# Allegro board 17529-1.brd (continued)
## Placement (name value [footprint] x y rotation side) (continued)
R2614  100R2F-L1-GP-U  [R402H14]  82.17 10.79 0 top
R2615  4K7R2J-2-GP  [R402H16]  87.44 10.22 270 top
R2616  2K2R2J-2-GP  [R402H16]  78.87 10.86 0 top
R2617  8K2R2F-1-GP  [R402H16]  85.72 12.7 180 top
R2618  20KR2J-L2-GP  [R402H16]  85.72 10.67 180 top
R2619  100KR2J-1-GP  [R402H16]  88.01 18.41 90 top
R2701  10KR2J-3-GP  [R402H16]  68.83 235.84 180 top
R2702  47KR2J-2-GP  [R402H16]  74.37 225.3 0 top
R2703  33R2J-2-GP  [R402H16]  61.52 223.85 270 top
R2704  4K7R2J-2-GP  [R402H16]  73.23 225.3 0 top
R2705  0R0603-PAD-2-GP-U  [0R0603-PAD-1-U]  58.42 230 0 bottom
R2706  100KR2F-L1-GP  [R402H16]  50.86 231.01 90 top
R2707  100KR2F-L1-GP  [R402H16]  50.86 232.16 90 top
R2708  0R0603-PAD-2-GP-U  [0R0603-PAD-1-U]  50.93 233.3 90 top
R2709  100KR2F-L1-GP  [R402H16]  53.72 231.01 0 top
R2710  200KR2F-L-GP  [R402H16]  54.74 231.01 0 top
R2711  100KR2F-L1-GP  [R402H16]  53.72 232.92 180 top
R2712  200KR2F-L-GP  [R402H16]  54.74 232.92 180 top
R2713  0R0603-PAD-2-GP-U  [0R0603-PAD-1-U]  76.2 230.5 270 top
R2714  220KR2F-GP  [R402H16]  79.63 235.46 90 top
R2715  0R2J-2-GP  [R402H16]  79.63 233.43 90 top
R2716  10KR2J-3-GP  [R402H16]  79.63 234.44 270 top
R2717  10KR2J-3-GP  [R402H16]  51.44 225.04 0 top
R2718  1KR2J-1-GP  [R402H16]  65.02 224.6 0 top
R2719  1KR2J-1-GP  [R402H16]  51.21 228.5 180 top
R2901  2K2R2J-2-GP  [R402H16]  70.23 227.33 90 top
R2902  1KR2J-1-GP  [R402H16]  72.77 227.33 270 top
R2903  4K7R2J-2-GP  [R402H16]  67.69 241.3 90 top
R2904  4K7R2J-2-GP  [R402H16]  67.69 240.28 90 top
R2905  10R2F-L-GP  [R402H14]  71.75 241.81 180 top
R2906  10R2F-L-GP  [R402H14]  71.75 239.78 0 top
R2907  22KR2J-GP  [R402H16]  68.71 242.82 180 top
R2908  1KR2J-1-GP  [R402H16]  77.09 239.4 180 top
R2909  22KR2J-GP  [R402H16]  75.95 242.57 180 top
R2910  1KR2J-1-GP  [R402H16]  76.58 237.87 270 top
R3001  75R2F-2-GP  [R402H16]  12.37 21.92 180 top
R3002  75R2F-2-GP  [R402H16]  11.96 24.85 180 top
R3003  22KR2J-GP  [R402H16]  11.35 21.93 0 top
R3004  22KR2J-GP  [R402H16]  10.95 24.85 0 top
R3005  75R2F-2-GP  [R402H16]  21.08 29.34 0 top
R3006  75R2F-2-GP  [R402H16]  18.03 29.34 0 top
R3007  22KR2J-GP  [R402H16]  18.35 19.3 270 top
R3008  1KR2J-1-GP  [R402H16]  20.07 29.59 0 top
R3009  22KR2J-GP  [R402H16]  18.41 22.35 270 top
R3010  1KR2J-1-GP  [R402H16]  19.05 29.59 0 top
R3011  2K2R2J-2-GP  [R402H16]  17.02 32.08 0 top
R3012  2K2R2J-2-GP  [R402H16]  13.97 32.08 0 top
R3013  75R2F-2-GP  [R402H16]  16 32.08 0 top
R3014  75R2F-2-GP  [R402H16]  14.99 32.08 0 top
R3015  22KR2J-GP  [R402H16]  13.97 30.2 0 top
R3016  22KR2J-GP  [R402H16]  17.02 30.2 0 top
R3101  2K49R2F-GP  [R402H16]  134.37 37.59 90 top
R3102  0R0402-PAD-2-GP  [0R0402-PAD-1]  146.69 41.27 90 top
R3103  1KR2F-3-GP  [R402H16]  144.37 46.69 270 top
R3104  1MR3F-GP  [R603H22]  135.97 42.95 180 top
R3105  0R0603-PAD-2-GP-U  [0R0603-PAD-1-U]  133.86 49.4 180 top
R3106  15KR2F-GP  [R402H16]  142.37 45.47 270 top
R3107  680R2F-GP  [R402H16]  134.85 42.24 0 top
R3201  249R2F-GP  [R402H16]  130.96 32.74 180 top
R3202  249R2F-GP  [R402H16]  129.9 32.74 180 top
R3203  0R1210-PAD-GP  [0R1210-4P-PAD]  137.31 32.95 90 top
R3204  510R3J-2-GP  [R603H22]  132.49 33.03 180 top
R3205  0R1210-PAD-GP  [0R1210-4P-PAD]  139.47 32.95 90 top
R3206  0R1210-PAD-GP  [0R1210-4P-PAD]  141.97 32.94 90 top
R3207  0R1210-PAD-GP  [0R1210-4P-PAD]  144.15 32.94 90 top
R3301  0R0402-PAD-2-GP  [0R0402-PAD-1]  40.39 238 270 top
R3302  6K2R2F-GP  [R402H16]  37.97 228.09 0 top
R3303  0R1210-PAD-GP  [0R1210-4P-PAD]  40.01 226.06 270 top
R3801  0R1210-PAD-GP  [0R1210-4P-PAD]  95.38 235.33 90 top
R3802  0R1210-PAD-GP  [0R1210-4P-PAD]  105.66 235.43 90 top
R3804  0R1210-PAD-GP  [0R1210-4P-PAD]  93.09 235.33 90 top
R3806  0R1210-PAD-GP  [0R1210-4P-PAD]  103.38 235.43 90 top
R3807  10KR2J-3-GP  [R402H16]  107.95 236.27 270 top
R3808  10KR2J-3-GP  [R402H16]  107.95 238.43 90 top
R3809  10KR2J-3-GP  [R402H16]  114.3 238.38 90 top
R3810  22KR2F-GP  [R402H16]  114.3 240.66 90 top
R3811  4K7R2J-2-GP  [R402H16]  110.49 235.46 180 top
R3812  10KR2J-3-GP  [R402H16]  107.95 237.41 90 top
R3813  10KR2J-3-GP  [R402H16]  114.3 236.35 90 top
R3814  0R0402-PAD-2-GP  [0R0402-PAD-1]  114.3 239.52 90 top
R3815  0R2J-2-GP  [R402H16]  111.51 235.46 180 top
R3816  0R2J-2-GP  [R402H16]  107.95 235.13 90 top
R3817  0R2J-2-GP  [R402H16]  114.3 237.36 270 top
R3818  4K7R2J-2-GP  [R402H16]  112.52 235.46 0 top
R4001  10KR2J-3-GP  [R402H16]  96.29 23.34 0 top
R4002  100KR2J-1-GP  [R402H16]  187.63 175.54 180 top
R4003  20KR2J-L2-GP  [R402H16]  89.09 24.77 90 top
R4004  100KR2J-1-GP  [R402H16]  153.8 33.02 0 top
R4005  22KR2J-GP  [R402H16]  99.21 23.22 180 top
R4006  0R0402-PAD-2-GP  [0R0402-PAD-1]  98.07 23.22 180 top
R4007  0R0402-PAD-2-GP  [0R0402-PAD-1]  98.3 28.45 270 top
R4008  0R0402-PAD-2-GP  [0R0402-PAD-1]  187.63 173.51 180 top
R4009  0R0402-PAD-2-GP  [0R0402-PAD-1]  154.05 26.16 180 top
R4010  0R0402-PAD-2-GP  [0R0402-PAD-1]  153.8 19.18 180 top
R4011  22KR2J-GP  [R402H16]  79.71 21.72 90 top
R4013  0R0402-PAD-2-GP  [0R0402-PAD-1]  92.13 22.2 90 top
R4014  249R2F-GP  [R402H16]  76.56 24.33 270 top
R4015  0R0402-PAD-2-GP  [0R0402-PAD-1]  79.73 20.62 90 top
R4016  249R2F-GP  [R402H16]  76.56 25.48 270 top
R4017  8K2R2F-1-GP  [R402H16]  150.24 204.14 90 top
R4018  8K2R2F-1-GP  [R402H16]  146.56 197.1 180 top
R4019  0R0402-PAD-2-GP  [0R0402-PAD-1]  153.29 203.96 90 top
R4020  10KR2J-3-GP  [R402H16]  146.81 204.6 90 top
R4021  0R0402-PAD-2-GP  [0R0402-PAD-1]  147.57 197.1 0 top
R4022  10KR2J-3-GP  [R402H16]  151.51 198.5 180 top
R4023  1KR2J-1-GP  [R402H16]  149.48 198.5 180 top
R4024  0R0402-PAD-2-GP  [0R0402-PAD-1]  144.27 197.1 0 top
R4025  0R0402-PAD-2-GP  [0R0402-PAD-1]  44.2 186.69 180 top
R4026  0R0402-PAD-2-GP  [0R0402-PAD-1]  45.21 186.69 0 top
R4201  0R0402-PAD-2-GP  [0R0402-PAD-1]  87.63 215.65 90 top
R4202  0R0402-PAD-2-GP  [0R0402-PAD-1]  87.63 214.5 90 top
R4203  47KR2J-2-GP  [R402H16]  100.79 211.4 270 top
R4204  10KR2J-3-GP  [R402H16]  96.16 210.24 270 top
R4205  4K7R2J-2-GP  [R402H16]  95.25 207.9 180 top
R4206  100KR2J-1-GP  [R402H16]  102.49 209.45 180 top
R4207  10KR2J-3-GP  [R402H16]  103.68 211 90 top
R4208  220KR2F-GP  [R402H16]  184.25 214.15 0 top
R4209  22KR2F-GP  [R402H16]  194.82 216.15 180 top
R4210  22KR2F-GP  [R402H16]  183.11 214.15 180 top
R4211  200KR2J-L1-GP  [R402H16]  175.21 215.93 270 top
R4212  100KR2F-L1-GP  [R402H16]  174.75 219.58 0 top
R4213  10KR2J-3-GP  [R402H16]  181.23 219.46 90 top
R4214  0R2J-2-GP  [R402H16]  175.21 218.01 270 top
R4215  22KR2F-GP  [R402H16]  175.21 216.99 90 top
R4216  10KR2J-3-GP  [R402H16]  179.71 213.36 90 top
R4217  10KR2F-2-GP  [R402H16]  171.83 220.85 180 top
R4218  100KR2J-1-GP  [R402H16]  175.21 214.83 270 top
R4219  10KR2F-2-GP  [R402H16]  171.45 215.01 270 top
R4302  0R0402-PAD-2-GP  [0R0402-PAD-1]  221.11 215.14 90 top
R4303  0R2J-2-GP  [R402H16]  221.11 216.15 90 top
R4304  10KR2F-2-GP  [R402H16]  215.01 215.26 0 top
R4305  10KR2J-3-GP  [R402H16]  221.11 214 270 top
R4801  10KR2J-3-GP  [R402H16]  134.62 85.72 270 top
R4802  47KR2J-2-GP  [R402H16]  137.92 88.9 270 top
R4803  10KR2J-3-GP  [R402H16]  137.92 87.76 90 top
R5001  0R2J-2-GP  [R402H16]  49.25 186.69 0 top
R5002  0R2J-2-GP  [R402H16]  50.37 186.69 0 top
R5003  0R0402-PAD-2-GP  [0R0402-PAD-1]  51.56 186.69 180 top
R5101  0R0402-PAD-2-GP  [0R0402-PAD-1]  233.22 156.64 0 top
R5301  D15R2010F-GP  [R2010-2H28]  176.15 7.37 180 top
R5302  0R0603-PAD-2-GP-U  [0R0603-PAD-1-U]  179.71 5.71 90 top
R5303  1K96R2F-1-GP  [R402H16]  181.61 13.59 90 top
R5304  16K9R2F-GP  [R402H16]  179.71 13.59 270 top
R5305  4K7R2J-2-GP  [R402H16]  186.31 14.73 180 top
R5601  470R2J-2-GP  [R402H16]  36.3 21.41 180 top
R5602  470R2J-2-GP  [R402H16]  36.3 19.51 0 top
R5603  470R2J-2-GP  [R402H16]  32.89 21.95 270 top
R5604  470R2J-2-GP  [R402H16]  34.8 21.95 90 top
R5605  470R2J-2-GP  [R402H16]  30.07 23.04 270 top
R5606  470R2J-2-GP  [R402H16]  31.98 23.04 90 top
R5607  470R2J-2-GP  [R402H16]  27.23 21.97 270 top
R5608  470R2J-2-GP  [R402H16]  29.13 21.97 90 top
R5609  20KR2F-L-GP  [R402H16]  21.97 15.62 0 top
R5610  1MR2J-1-GP  [R402H16]  23.11 24.21 270 top
R5901  4K7R2J-2-GP  [R402H16]  55.03 23.38 180 top
R5902  4K7R2J-2-GP  [R402H16]  53.95 23.39 180 top
R5903  4K7R2J-2-GP  [R402H16]  68.53 22.38 270 top
R5904  4K7R2J-2-GP  [R402H16]  68.55 23.57 90 top
R5905  4K7R2J-2-GP  [R402H16]  57 25.91 90 top
R5906  4K7R2J-2-GP  [R402H16]  57 24.87 90 top
R5907  4K7R2J-2-GP  [R402H16]  57.4 23.37 180 top
R5908  4K7R2J-2-GP  [R402H16]  55.52 26.31 0 top
R5909  4K7R2J-2-GP  [R402H16]  55.93 28.4 180 top
R5910  100KR2J-1-GP  [R402H16]  67.51 25.37 90 top
R5911  0R0402-PAD-2-GP  [0R0402-PAD-1]  70.89 25.27 180 top
R5912  0R0402-PAD-2-GP  [0R0402-PAD-1]  71.96 25.27 180 top
R5913  75R2F-2-GP  [R402H16]  61.21 18.27 270 top
R5914  75R2F-2-GP  [R402H16]  63.13 18.29 270 top
R5915  75R2F-2-GP  [R402H16]  65.05 18.28 90 top
R5916  47R2F-GP  [R402H16]  57.53 15.24 0 top
R5917  47R2F-GP  [R402H16]  58.67 17.91 0 top
R5918  4K7R2J-2-GP  [R402H16]  69.82 25.27 0 top
R5919  4K7R2J-2-GP  [R402H16]  72.39 23.8 270 top
R5920  10KR2F-2-GP  [R402H16]  42.29 16.26 90 top
R5921  100KR2J-1-GP  [R402H16]  42.29 15.11 270 top
R6202  0R2J-2-GP  [R402H16]  151.18 140.97 180 top
R6203  0R2J-2-GP  [R402H16]  152.32 140.97 180 top
R6301  60K4R2F-GP  [R402H16]  224.05 175.59 0 top
R6302  75KR2F-GP  [R402H16]  224.08 177.95 180 top
R6304  10KR2J-3-GP  [R402H16]  194.41 126.21 0 top
R6306  10KR2J-3-GP  [R402H16]  209.22 210.24 0 top
R6308  0R3J-0-U-GP  [R603H22]  207.26 213.97 90 top
R6311  10KR2J-3-GP  [R402H16]  215.8 202.16 270 top
R6312  10KR2J-3-GP  [R402H16]  215.8 201.09 270 top
R6313  10KR2J-3-GP  [R402H16]  204.98 214.05 270 top
R6314  10KR2J-3-GP  [R402H16]  197.18 206.73 270 top
R6315  75KR2F-GP  [R402H16]  196.75 208.2 0 top
R6316  20KR2F-L-GP  [R402H16]  214.55 120.5 90 top
R6317  20KR2F-L-GP  [R402H16]  212.09 118.16 0 top
R6318  10KR2J-3-GP  [R402H16]  216.08 177.42 90 top
R6319  0R2J-2-GP  [R402H16]  222.15 176.02 90 top
R6320  0R2J-2-GP  [R402H16]  222.17 178.64 90 top
R6401  4K7R2J-2-GP  [R402H16]  23.34 233.86 270 top
R6402  10KR2J-3-GP  [R402H16]  223.16 146.43 270 top
R6403  10KR2J-3-GP  [R402H16]  224.64 150.01 180 top
R6404  10KR2J-3-GP  [R402H16]  225.3 152.37 270 top
R6405  33R2J-2-GP  [R402H16]  21.82 234.37 0 top
R6406  10KR2J-3-GP  [R402H16]  221.69 146.86 180 top
R6407  10KR2J-3-GP  [R402H16]  223.14 150.44 90 top
R6408  10KR2J-3-GP  [R402H16]  221.39 152.45 90 top
R6409  150R6J-1-GP  [R1206H26]  19.3 233.02 0 top
R6410  4K7R2J-2-GP  [R402H16]  16.51 228.5 180 top
R6411  10KR2J-3-GP  [R402H16]  16.51 230.4 0 top
R6412  4K7R2J-2-GP  [R402H16]  17.53 228.5 180 top
R6413  100R6J-3-GP  [R1206H24]  13.49 232.97 180 top
R6414  10KR2J-3-GP  [R402H16]  17.53 230.4 0 top
R6416  10KR2J-3-GP  [R402H16]  27.05 239.52 90 top
R6418  360R3-GP  [R603H22]  26.67 244.47 270 top
R6420  10KR2J-3-GP  [R402H16]  23.75 240.16 90 top
R6421  10KR2J-3-GP  [R402H16]  21.84 240.16 90 top
R6422  10KR2J-3-GP  [R402H16]  225.07 148.54 270 top
R6423  10KR2J-3-GP  [R402H16]  223.16 149.35 90 top
R6801  0R2J-2-GP  [R402H16]  218.31 103.12 90 top
R6802  0R2J-2-GP  [R402H16]  218.31 102.11 90 top
R9101  0R3J-0-U-GP  [R603H22]  198.12 180.85 90 top
R9104  0R3J-0-U-GP  [R603H22]  208.91 183.26 270 top
R9105  33R2J-2-GP  [R402H16]  209.42 173.99 270 top
R9106  33R2J-2-GP  [R402H16]  205.87 172.59 180 top
R9107  33R2J-2-GP  [R402H16]  203.58 172.64 180 top
R9108  0R0402-PAD-2-GP  [0R0402-PAD-1]  204.72 172.64 180 top
R9110  10KR2J-3-GP  [R402H16]  201.73 177.52 0 top
R9111  0R2J-2-GP  [R402H16]  200.63 177.52 0 top
R9112  0R0402-PAD-2-GP  [0R0402-PAD-1]  193.7 169.65 270 top
R9113  10KR2J-3-GP  [R402H16]  208.91 171.04 270 top
R9201  0R2J-2-GP  [R402H16]  216.66 38.73 270 top
R9202  0R2J-2-GP  [R402H16]  216.66 39.88 270 top
R9203  22R2J-2-GP  [R402H16]  215.72 52.32 0 top
R9204  8K2R2J-3-GP  [R402H16]  231.01 88.65 270 top
R9205  8K2R2J-3-GP  [R402H16]  231.01 89.79 270 top
R9301  0R0402-PAD-2-GP  [0R0402-PAD-1]  188.9 108.2 270 top
R9401  0R0402-PAD-2-GP  [0R0402-PAD-1]  156.46 35.37 0 top
R9402  0R0402-PAD-2-GP  [0R0402-PAD-1]  197.1 42.16 90 top
R9403  0R0603-PAD-2-GP-U  [0R0603-PAD-1-U]  211.46 29.72 270 top
R9501  10KR2J-3-GP  [R402H16]  197.99 66.67 180 top
R9502  33R2J-2-GP  [R402H16]  192.35 62.87 270 top
R9503  33R2J-2-GP  [R402H16]  192.35 61.8 270 top
R9504  49D9R2F-GP  [R402H16]  190.86 63.3 180 top
R9505  49D9R2F-GP  [R402H16]  190.86 61.37 0 top
R9506  12KR3-GP  [R603H22]  192.18 56.87 270 top
R9507  10KR2J-3-GP  [R402H16]  216.46 60.55 90 top
R9508  22R2J-2-GP  [R402H16]  208.28 67.44 180 top
R9509  10KR2J-3-GP  [R402H16]  200.43 67.36 90 top
R9510  10KR2J-3-GP  [R402H16]  216.46 61.62 90 top
R9511  10KR2J-3-GP  [R402H16]  216.46 62.69 90 top
R9512  10KR2J-3-GP  [R402H16]  196.44 66.22 270 top
R9901  0R0402-PAD-2-GP  [0R0402-PAD-1]  141.96 64.41 90 top
R9902  0R0402-PAD-2-GP  [0R0402-PAD-1]  140.06 64.41 270 top
R9903  1KR2J-1-GP  [R402H16]  132.14 62.48 90 top
R9904  0R2J-2-GP  [R402H16]  149.73 63.37 0 bottom
R9905  0R2J-2-GP  [R402H16]  132.59 61.02 0 bottom
R9906  1KR2J-1-GP  [R402H16]  135.95 61.34 270 top
R9907  1KR2J-1-GP  [R402H16]  136.65 61.28 0 bottom
R9908  1KR2J-1-GP  [R402H16]  135.64 61.28 0 bottom
R9909  2K2R2J-2-GP  [R402H16]  136.14 74.74 180 top
R9910  1KR2J-1-GP  [R402H16]  133.86 74.74 180 top
R9911  0R2J-2-GP  [R402H16]  137.29 74.74 180 top
R9912  150R2F-1-GP  [R402H16]  132.14 61.34 90 top
R9913  1KR2J-1-GP  [R402H16]  134.05 61.34 270 top
R9914  0R2J-2-GP  [R402H16]  130.18 70.55 0 top
R9915  51R2J-2-GP  [R402H16]  127 73.47 0 top
R9916  0R0402-PAD-2-GP  [0R0402-PAD-1]  238.84 104.7 0 top
R9917  0R0402-PAD-2-GP  [0R0402-PAD-1]  225.17 109.83 90 top
R9918  0R0402-PAD-2-GP  [0R0402-PAD-1]  237.34 107.47 0 top
R9919  0R0402-PAD-2-GP  [0R0402-PAD-1]  236.35 109.91 270 top
R9920  0R0402-PAD-2-GP  [0R0402-PAD-1]  228.37 109.86 90 top
R9921  0R0402-PAD-2-GP  [0R0402-PAD-1]  231.83 109.93 90 top
R9922  2K2R2J-2-GP  [R402H16]  131.57 56.52 270 top
RJ45R1  SKT-RJ45-USB-87-GP  [RUA1JA-KJKC-DE0-0R]  131.5 19.37 0 top
RN1601  SRN10KJ-12-GP  [ARES8-CN24-UH22]  206.91 164.16 0 top
RN2401  SRN8K2J-4-GP  [ARES8-CN24H20]  202.51 81.28 180 top
RN2402  SRN8K2J-4-GP  [ARES8-CN24H20]  193.37 81.25 180 top
RN2403  SRN8K2J-4-GP  [ARES8-CN24H20]  197.23 81.25 180 top
RN2501  SRN33J-5-GP-U  [SMD-ARES4H18]  184.1 190.83 0 top
RN2502  SRN33J-7-GP-U  [ARES8-CN24-UH20]  191.13 189.51 180 top
RN5601  SRN2K2J-1-GP  [ARES2H16]  24 16.64 270 top
RN5901  SRN2K2J-1-GP  [ARES2H16]  56.52 21.34 270 top
RN9501  SRN8K2J-3-GP  [SMD-ARES4]  209.8 67.69 0 top
RN9502  SRN8K2J-3-GP  [SMD-ARES4]  206.5 67.69 0 top
RN9503  SRN8K2J-4-GP  [ARES8-CN24H20]  207.49 45.69 180 top
RN9504  SRN8K2J-4-GP  [ARES8-CN24H20]  215.26 46.35 180 top
RN9505  SRN8K2J-4-GP  [ARES8-CN24H20]  204.09 67.82 0 top
RN9506  SRN8K2J-4-GP  [ARES8-CN24H20]  215.49 42.32 270 top
SATA1  SKT-SATA7P-168-GP  [LE18077-Z55D-4F]  127.5 189.64 0 top
SATA2  SKT-SATA7P-29-GP-U  [ABA-SAT-010-K04-U]  105.6 189.64 0 top
SATA3  SKT-SATA7P-169-GP  [LE18077-Z55D-4F]  127.5 200.24 0 top
SATA4  SKT-SATA7P-169-GP  [LE18077-Z55D-4F]  105.6 200.24 0 top
SATAP1  PIN-CONN6B-S1-GP  [733-71-06TB18]  146 221 180 top
SATAP2  PIN-CONN6B-S1-GP  [733-71-06TB18]  184 222 180 top
SB1  CANON-LAKE-GP  [BGA874M250240H60]  201.7 145 90 top
SD1  SKT-SDCARD-61-GP  [WK21921-151146-7H]  47.7 245.1 180 top
SLOT1  PCISLT36-7-GP  [AAA-PCI-003-K45]  162.01 31.77 90 top
SLOT2  PCISLT164-187-GP  [AAA-PCI-190-K10]  182.33 31.77 270 top
SLOT3  PCISLT36-7-GP  [AAA-PCI-003-K45]  202.65 31.77 90 top
SLOT4  PCISLT120-31-GP  [10-00870-1A61-A]  222.97 78.82 270 top
SSKT1  SKT-91960-0084L-GP  [SKT-SOIC8-1H211]  188.34 199.97 90 top
SSKT2  SKT-SPI16P-7-GP  [SKT-SOIC16-153139H258]  188.07 199.64 0 top
TC1101  E820U2D5VM-6-GP  [ECAP-100D6D3H375]  77.65 159.99 180 top
TC3201  E220U16VM-L8-GP  [ECAP-100D6D3H493]  116.2 21.21 180 top
TC3801  E220U16VM-L8-GP  [ECAP-100D6D3H493]  86.23 236.98 180 top
TC3901  E220U16VM-L8-GP  [ECAP-100D6D3H493]  95 10.67 180 top
TC5301  E220U16VM-L8-GP  [ECAP-100D6D3H493]  207.92 9.35 180 top
TP401  TPAD28-2-GP  [TPAD28]  85.02 99.63 180 bottom
TP402  TPAD28-2-GP  [TPAD28]  85.32 101.22 180 bottom
TP403  TPAD28-2-GP  [TPAD28]  88.42 96.93 180 bottom
TP404  TPAD28-2-GP  [TPAD28]  85.6 92.84 180 bottom
TP405  TPAD28-2-GP  [TPAD28]  84.07 93.95 180 bottom
TP406  TPAD28-2-GP  [TPAD28]  83.85 96.01 180 bottom
TP407  TPAD28-2-GP  [TPAD28]  81.74 93.79 180 bottom
TP408  TPAD28-2-GP  [TPAD28]  81.31 101.41 180 bottom
TP409  TPAD28-2-GP  [TPAD28]  76.76 98.18 180 bottom
TP410  TPAD28-2-GP  [TPAD28]  77.68 100.44 180 bottom
TP411  TPAD28-2-GP  [TPAD28]  83.95 100.34 180 bottom
TP412  TPAD28-2-GP  [TPAD28]  82.05 100.42 180 bottom
TP413  TPAD28-2-GP  [TPAD28]  83.04 101.46 180 bottom
TP414  TPAD28-2-GP  [TPAD28]  76.69 99.5 180 bottom
TP415  TPAD28-2-GP  [TPAD28]  79.4 97.85 180 bottom
TP416  TPAD28-2-GP  [TPAD28]  80.12 101.94 180 bottom
TP601  TPAD28-2-GP  [TPAD28]  58.14 113.72 180 bottom
TP701  TPAD28-2-GP  [TPAD28]  85.72 94.11 180 bottom
TP901  TPAD28-2-GP  [TPAD28]  61.68 113.34 180 bottom
TP902  TPAD28-2-GP  [TPAD28]  35.69 119.13 0 top
TP903  TPAD28-2-GP  [TPAD28]  91.31 101.47 180 bottom
TP904  TPAD28-2-GP  [TPAD28]  62.72 112.23 180 bottom
TP905  TPAD28-2-GP  [TPAD28]  61.22 111.64 180 bottom
TP906  TPAD28-2-GP  [TPAD28]  75.29 119.2 180 bottom
TP907  TPAD28-2-GP  [TPAD28]  85.34 90.81 180 bottom
TP1501  TPAD28-2-GP  [TPAD28]  204.42 151.08 180 bottom
TP1504  TPAD28-2-GP  [TPAD28]  212.7 143.51 180 bottom
TP1505  TPAD28-2-GP  [TPAD28]  214.73 141.43 180 bottom
TP1506  TPAD28-2-GP  [TPAD28]  214.15 132.21 180 bottom
TP2001  TPAD28-2-GP  [TPAD28]  223.7 155.91 0 top
TP2101  TPAD28-2-GP  [TPAD28]  193.17 161.16 0 top
TP2102  TPAD28-2-GP  [TPAD28]  194.31 160.66 0 top
TP2201  TPAD28-2-GP  [TPAD28]  203.58 140.51 180 bottom
TP2202  TPAD28-2-GP  [TPAD28]  203.61 139.29 180 bottom
TP2501  TPAD28-2-GP  [TPAD28]  132.49 221.18 180 bottom
TP2502  TPAD28-2-GP  [TPAD28]  136.5 219.25 180 bottom
TP3101  -  [TPAD30]  132.49 35.03 270 top
TP3102  -  [TPAD30]  131.06 34.34 270 top
TP3103  -  [TPAD30]  129.79 34.39 270 top
TP9106  -  [TPAD30]  206.76 182.63 0 top
TR3201  FILTER-4P-156-GP-U  [L125100-4PH24]  146.82 32.97 180 top
TR3202  FILTER-4P-156-GP-U  [L125100-4PH24]  149.1 32.97 180 top
TR3801  FILTER-4P-156-GP-U  [L125100-4PH24]  98.09 235.33 0 top
TR3802  FILTER-4P-156-GP-U  [L125100-4PH24]  100.38 235.33 0 top
TR3901  FILTER-4P-156-GP-U  [L125100-4PH24]  105.16 24 180 top
TR3902  FILTER-4P-156-GP-U  [L125100-4PH24]  107.44 24 180 top
TR5601  FILTER-4P-172-GP  [L125100-4PH26]  33.4 18.49 0 top
TR5602  FILTER-4P-172-GP  [L125100-4PH26]  31.24 18.49 0 top
TR5603  FILTER-4P-172-GP  [L125100-4PH26]  29.08 18.49 0 top
TR5604  FILTER-4P-172-GP  [L125100-4PH26]  26.92 18.49 0 top
U401  MMDT3904-2-GP  [SOT-363-1H44]  10.92 186.31 0 top
U2001  74AUP1G97GW-GP  [SOT-363H44]  221.62 182.45 180 top
U2002  SN74AUP1G74DCUR-GP  [SSOIC8-4H36]  228.07 184.38 0 top
U2003  74AUP1G97GW-GP  [SOT-363H44]  224.74 182.42 0 top
U2401  SCH5553-NU-GP  [PFPCC128-5H48]  203 93.07 270 top
U2402  74AUP1G97GW-GP  [SOT-363H44]  212.57 78.66 0 top
U2403  SN74LVC1G14DCKR-1-GP  [SC70-5H44]  212.98 75.34 270 top
U2404  2N7002KDW-1-GP  [SOT-363H44]  214.25 72.26 90 top
U2405  TC7SZ32FU-2-GP  [SC70-5H44]  214.5 69.09 90 top
U2501  MX25L25673GM2I-08G-GP  [SOIC8-1H86]  188.34 199.95 270 top
U2502  MX25L25673GMI-10G-GP  [SOIC16-6H105]  188.08 199.62 180 top
U2601  G709T1UF-GP  [SOT-23-5H56]  107.52 65.61 180 top
U2602  SNLVC1G08DCKRG4-GP  [SC70-5H44]  88.39 16.26 270 top
U2701  ALC3820-CG-GP  [LQFP48H63]  62.61 231.14 180 top
U3101  RTL8111G-CGT-1-GP-U2  [QFN32J4-G2D85H36]  140.56 40.94 180 top
U3201  G524B1T11U-GP  [SOT-23-5H58]  110.36 20.95 180 top
U3301  RTS5170-GR-GP  [QFN24-G2D5H40-U]  40.51 233.17 180 top
U3801  G524B1T11U-GP  [SOT-23-5H58]  86.61 230.5 180 top
U3901  G524B1T11U-GP  [SOT-23-5H58]  97.41 17.4 0 top
U4001  74AHC1G08DCKR-GP  [SC70-5H44]  189.79 174.52 180 top
U4002  2N7002KDW-1-GP  [SOT-363H44]  84.76 22.86 90 top
U4003  2N7002K-2-GP  [SOT23DGS2D4H44]  88.57 22.48 270 top
U4004  74AHC1G08DCKR-GP  [SC70-5H44]  154.43 36.07 0 top
U4005  74AUP1G97GW-GP  [SOT-363H44]  97.33 26.09 0 top
U4006  74AHC1G08DCKR-GP  [SC70-5H44]  154.43 29.21 0 top
U4007  74AHC1G08DCKR-GP  [SC70-5H44]  154.43 22.23 0 top
U4008  74AUP1G97GW-GP  [SOT-363H44]  92.26 24.39 270 top
U4009  SNLVC1G08DCKRG4-GP  [SC70-5H44]  79.68 23.88 270 top
U4010  SNLVC1G08DCKRG4-GP  [SC70-5H44]  145.03 201.42 0 top
U4201  AOZ2331DI-1-GP  [SON14J3020-G2610H32]  91.52 215.47 90 top
U4202  2N7002KDW-1-GP  [SOT-363H44]  99.95 209.32 90 top
U4203  AON7401-GP  [PPAK-8P-3232H36]  203.28 218.54 270 top
U4301  74AUP1G97GW-GP  [SOT-363H44]  216.79 219.07 270 top
U4801  2N7002KDW-1-GP  [SOT-363H44]  135.13 87.88 270 top
U5301  MC34063ADR2G-GP  [SOIC8H69]  182.88 9.27 90 top
U5601  2N7002KDW-1-GP  [SOT-363H44]  25.58 24.28 0 top
U5602  AP2331SA-7-GP  [SOT23-2D4-312H48]  39.24 11.05 0 top
U5901  RTD2166-CGT-GP  [QFN32J4-G2D85H36]  62.22 22.25 0 top
U6301  RT9724GB-GP  [SOT-23-5H51]  206.38 211.07 90 top
U6302  2N7002K-2-GP  [SOT23DGS2D4H44]  198.12 212.09 0 top
U6305  2N7002K-2-GP  [SOT23DGS2D4H44]  215.95 180.42 0 top
U6401  2N7002KDW-1-GP  [SOT-363H44]  26.42 242.06 180 top
U6402  2N7002KDW-1-GP  [SOT-363H44]  22.99 242.32 90 top
U9101  NPCT750JAAYX-1-GP  [QFN32G5-G3D6H32]  205.99 178.44 0 top
U9501  IT8893E-FX-GP  [LQFP128H63]  204.65 56.49 90 top
UC3201  SCD01U50V2KX-1DLGP  [C402H22]  145.26 19.84 0 top
UC3202  SCD1U16V2KX-3DLGP  [C402H22]  145.24 22.78 180 top
UC3203  SCD1U16V2KX-3DLGP  [C402H22]  110.87 23.88 270 top
UC3801  SCD1U16V2KX-3DLGP  [C402H22]  90.93 239.01 90 top
UC3901  SCD1U16V2KX-3DLGP  [C402H22]  94.49 15.49 270 top
USB2R1  SKT-USB12-24-GP  [SKT-USB12-157183]  109.59 9.53 0 top
USB3F1  SKT-USB11-153-GP  [SKT-USB11-138166]  88.2 247.3 180 top
USB3F2  SKT-USB11-153-GP  [SKT-USB11-138166]  109 247.3 180 top
VGA1  D-SUB-15-295-GP  [VDS075W-D307-00A3F2B]  59.85 4.17 0 top
X1801  XTAL-24MHZ-182-GP  [OSC-3225-4P-3H36]  198.63 126.34 0 top
X1802  XTAL-32D768KHZ-88-GP  [SMD49-3215-0713H36]  217.55 168.02 270 top
X3101  XTAL-25MHZ-202-GP  [SMD-OSC38H20]  132.08 43.18 270 top
XDP1  DM-SMC-CONN60A-GP-01  [DM-BSH-03001-FDA-01]  137.67 70.87 180 bottom

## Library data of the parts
APS1 = A1002WV0-13PS-5E: tolerance: 20.F1161.013
ATX2 = HM3502E-P1: tolerance: 20.81163.004
ATX3 = AT4203W-D067-08E801B-U: tolerance: 020.80375.0008
AUD1 = ABA-JAK-028-K03: tolerance: 22.10251.831
BT2501 = 20-00950-1A01-A-U: tolerance: 022.70019.0001
C301 C302 C304 C305 C601 C603 C805 C1101 C1102 C1105 C1106 C1109 C1202 C1205-C1208 C1210 C1213 C1216 C1701 C2002 C2003 C2005 C2101 C2102 C2104-C2107 C2113-C2117 C2406 C2408-C2410 C2415-C2423 C2425 C2704 C2707 C2708 C2712 C2714 C2716-C2718 C2721 C3101 C3103 C3105-C3108 C3111 C3113 C3301 C3307 C3806 C3807 C4001-C4008 C4010 C4011 C4212 C4213 C4216 C4305-C4307 C4309 C4311 C5101 C5302 C5612 C5613 C5902-C5906 C5908 C5909 C6203 C6205 C6213 C6301-C6304 C6309 C6310 C6402 C6403 C9102 C9103 C9105 C9106 C9201-C9209 C9310-C9312 C9403-C9405 C9408-C9410 C9506 C9510 C9513 C9516 C9519 C9522 C9523 C9901 PC4803 PC4810 PC4913 PC5205 UC3202 UC3203 UC3801 UC3901 = C402H22: tolerance: 78.10421.2FLDL
C402 C403 C803 C806 C1103 C1104 C1108 C1201 C1212 C2001 C4215 C4308 C4310 = C402H22: tolerance: 78.10421.L0L
C602 C1209 = C402H22: tolerance: 78.22321.2FLDL
C801 C1033 C1203 C1214 C1215 C2006 C2007 C2103 C2110 C2120-C2125 C2405 C2412 C2501 C3112 C3201 C3303 C3304 C3805 C3901 C4009 C4012 C4013 C4203 C4204 C6201 C6401 C9507 C9511 C9514 C9515 C9517 C9518 C9520 C9526 C9527 = C402H22: tolerance: 78.10523.5FLDL
C802 C4209 C4210 C5609 PC4407 PC4408 PC4410 PC4412 PC4420 PC4421 PC4428 PC4429 = C402H22: tolerance: 78.10422.5FLDL
C804 C2703 C2705 C2709-C2711 C2901 C3001 C3002 C3007 C3008 C4208 C5303 C5304 C6017-C6020 C6206 C6214 PC4501 PC4502 PC4506 PC4507 PC4511 PC4512 PC4516 PC4517 PC4601 PC4602 PC4606 PC4607 PC4702 PC4703 PC4901-PC4905 PC5004-PC5007 PC5102-PC5105 = C805H58: tolerance: 78.10622.51LDL
C1001 C1002 C2111 C2112 C2118 C2119 C2127 C2128 C6308 PC1046-PC1049 = C603H40: tolerance: 78.22610.5BLDL
C1004 C1005 C1024-C1027 = C805H58: tolerance: 78.22610.L2L
C1007-C1022 C1032 C2722 PC1034 PC1036-PC1040 PC1068 PC4808 PC4809 = C805H54: tolerance: 78.22610.51LDL
C1028-C1031 PC1035 PC1041-PC1045 PC1050-PC1053 = C805H54: tolerance: 78.47610.51LDL
C1107 C1204 C1211 C2108 C2109 C2411 C2414 C3102 C3104 C3114 C3302 C5907 = C603H36: tolerance: 78.47520.5BLDL
C1110 C1217 = C402H22: tolerance: 78.22510.5FLDL
C1801-C1804 = C402H22: tolerance: 78.15034.1FLDL
C2004 C2401 C2403 C2413 C2427 C2903 C2906 C2907 C3003-C3006 C3009 C3010 = C402H22: tolerance: 78.10134.1FLDL
C2126 C2424 C2706 C2713 C3117 C3306 C4205 C4206 C6307 C9101 C9104 C9411 C9508 C9512 C9521 C9524 C9525 = C603H36: tolerance: 78.10610.5BLDL
C2402 C2404 PC4405 PC4418 PC4812 = C402H22: tolerance: 78.22224.2FLDL
C2407 C2426 C9505 C9509 PC4403 PC4806 UC3201 = C402H22: tolerance: 78.10324.2FLDL
C2701 C2702 C5901 PC4402 = C603H36: tolerance: 78.22523.5BLDL
C2715 C5916-C5921 PC4914 PC4915 = C402H22: tolerance: 78.22034.1FLDL
C2719 C2720 PC4503 PC4508 PC4513 PC4518 PC4603 PC4608 PC4704 PC4906-PC4908 PC5008 PC5106 = C603H35: tolerance: 78.10424.2BLDL
C2902 C4207 C4211 = C805H56: tolerance: 78.10622.LAL
C2904 C2905 = C805H54: tolerance: 78.47522.51LDL
C3109 = C402H22: tolerance: 78.10421.2FLDL; signal model: Graser_C3109
C3110 = C402H22: tolerance: 78.10421.2FLDL; signal model: Graser_C3110
C3115 = C402H22: tolerance: 78.10421.2FLDL; signal model: Graser_C3115
C3116 = C402H22: tolerance: 78.10421.2FLDL; signal model: Graser_C3116
C3118 C3119 = C402H22: tolerance: 78.20034.1FLDL
C3305 = C402H22: tolerance: 78.6R874.1FLDL
C3801 = C402H22: tolerance: 78.10421.2FLDL; signal model: Graser_C3801
C3802 = C402H22: tolerance: 78.10421.2FLDL; signal model: Graser_C3802
C3803 = C402H22: tolerance: 78.10421.2FLDL; signal model: Graser_C3803
C3804 = C402H22: tolerance: 78.10421.2FLDL; signal model: Graser_C3804
C4201 C4202 PC4409 PC4416 PC4422 PC4427 PC4807 PC4911 PC4912 = C402H22: tolerance: 78.10224.2FLDL
C4214 = C402H22: tolerance: 78.10324.L0L
C4217 C4303 PC4401 PC4504 PC4509 PC4514 PC4519 PC4604 PC4609 PC4701 PC4705 PC4706 PC4804 PC4909 PC4910 PC4916 PC4917 PC5001-PC5003 PC5010 PC5101 PC5107 PC5109 PC5202 = C603H36: tolerance: 078.10524.05BD
C5301 C5610 C5611 PC4404 PC4414 PC4417 PC4426 = C402H22: tolerance: 78.47124.2FLDL
C5601 = C402H22: tolerance: 78.10421.2FLDL; signal model: Graser_C5601
C5602 = C402H22: tolerance: 78.10421.2FLDL; signal model: Graser_C5602
C5603 = C402H22: tolerance: 78.10421.2FLDL; signal model: Graser_C5603
C5604 = C402H22: tolerance: 78.10421.2FLDL; signal model: Graser_C5604
C5605 = C402H22: tolerance: 78.10421.2FLDL; signal model: Graser_C5605
C5606 = C402H22: tolerance: 78.10421.2FLDL; signal model: Graser_C5606
C5607 = C402H22: tolerance: 78.10421.2FLDL; signal model: Graser_C5607
C5608 = C402H22: tolerance: 78.10421.2FLDL; signal model: Graser_C5608
C5910 = C402H22: tolerance: 78.10421.2FLDL; signal model: Graser_C5910
C5911 = C402H22: tolerance: 78.10421.2FLDL; signal model: Graser_C5911
C5912 = C402H22: tolerance: 78.10421.2FLDL; signal model: Graser_C5912
C5913 = C402H22: tolerance: 78.10421.2FLDL; signal model: Graser_C5913
C5914 = C402H22: tolerance: 78.10421.2FLDL; signal model: Graser_C5914
C5915 = C402H22: tolerance: 78.10421.2FLDL; signal model: Graser_C5915
C5922 C5923 = C402H22: tolerance: 078.2R074.01FD
C6001 = C402H22: tolerance: 78.10324.2FLDL; signal model: Graser_C6001
C6002 = C402H22: tolerance: 78.10324.2FLDL; signal model: Graser_C6002
C6003 = C402H22: tolerance: 78.10324.2FLDL; signal model: Graser_C6003
C6004 = C402H22: tolerance: 78.10324.2FLDL; signal model: Graser_C6004
C6005 = C402H22: tolerance: 78.10324.2FLDL; signal model: Graser_C6005
C6006 = C402H22: tolerance: 78.10324.2FLDL; signal model: Graser_C6006
C6007 = C402H22: tolerance: 78.10324.2FLDL; signal model: Graser_C6007
C6008 = C402H22: tolerance: 78.10324.2FLDL; signal model: Graser_C6008
C6009 = C402H22: tolerance: 78.10324.2FLDL; signal model: Graser_C6009
C6010 = C402H22: tolerance: 78.10324.2FLDL; signal model: Graser_C6010
C6011 = C402H22: tolerance: 78.10324.2FLDL; signal model: Graser_C6011
C6012 = C402H22: tolerance: 78.10324.2FLDL; signal model: Graser_C6012
C6013 = C402H22: tolerance: 78.10324.2FLDL; signal model: Graser_C6013
C6014 = C402H22: tolerance: 78.10324.2FLDL; signal model: Graser_C6014
C6015 = C402H22: tolerance: 78.10324.2FLDL; signal model: Graser_C6015
C6016 = C402H22: tolerance: 78.10324.2FLDL; signal model: Graser_C6016
C6202 = C402H22: tolerance: 078.22423.05FD; signal model: Graser_C6202
C6204 = C402H22: tolerance: 078.22423.05FD; signal model: Graser_C6204
C6207 = C402H22: tolerance: 078.22423.05FD; signal model: Graser_C6207
C6208 = C402H22: tolerance: 078.22423.05FD; signal model: Graser_C6208
C6209 = C402H22: tolerance: 078.22423.05FD; signal model: Graser_C6209
C6210 = C402H22: tolerance: 078.22423.05FD; signal model: Graser_C6210
C6211 = C402H22: tolerance: 078.22423.05FD; signal model: Graser_C6211
C6212 = C402H22: tolerance: 078.22423.05FD; signal model: Graser_C6212
C6305 = C402H22: tolerance: 78.10421.2FLDL; signal model: Graser_C6305
C6306 = C402H22: tolerance: 78.10421.2FLDL; signal model: Graser_C6306
C9301 = C402H22: tolerance: 078.22423.05FD; signal model: Graser_C9301
C9302 = C402H22: tolerance: 078.22423.05FD; signal model: Graser_C9302
C9303 = C402H22: tolerance: 078.22423.05FD; signal model: Graser_C9303
C9304 = C402H22: tolerance: 078.22423.05FD; signal model: Graser_C9304
C9305 = C402H22: tolerance: 078.22423.05FD; signal model: Graser_C9305
C9306 = C402H22: tolerance: 078.22423.05FD; signal model: Graser_C9306
C9307 = C402H22: tolerance: 078.22423.05FD; signal model: Graser_C9307
C9308 = C402H22: tolerance: 078.22423.05FD; signal model: Graser_C9308
C9309 = C402H22: tolerance: 078.22423.05FD; signal model: Graser_C9309
C9313 = C402H22: tolerance: 078.22423.05FD; signal model: Graser_C9313
C9314 = C402H22: tolerance: 078.22423.05FD; signal model: Graser_C9314
C9315 = C402H22: tolerance: 078.22423.05FD; signal model: Graser_C9315
C9316 = C402H22: tolerance: 078.22423.05FD; signal model: Graser_C9316
C9317 = C402H22: tolerance: 078.22423.05FD; signal model: Graser_C9317
C9318 = C402H22: tolerance: 078.22423.05FD; signal model: Graser_C9318
C9319 = C402H22: tolerance: 078.22423.05FD; signal model: Graser_C9319
C9320 = C402H22: tolerance: 078.22423.05FD; signal model: Graser_C9320
C9321 = C402H22: tolerance: 078.22423.05FD; signal model: Graser_C9321
C9322 = C402H22: tolerance: 078.22423.05FD; signal model: Graser_C9322
C9323 = C402H22: tolerance: 078.22423.05FD; signal model: Graser_C9323
C9324 = C402H22: tolerance: 078.22423.05FD; signal model: Graser_C9324
C9325 = C402H22: tolerance: 078.22423.05FD; signal model: Graser_C9325
C9326 = C402H22: tolerance: 078.22423.05FD; signal model: Graser_C9326
C9328 = C402H22: tolerance: 078.22423.05FD; signal model: Graser_C9328
C9329 C9331 PC4918 PC4919 = C402H22: tolerance: 078.22423.05FD
C9332 = C402H22: tolerance: 078.22423.05FD; signal model: Graser_C9332
C9334 = C402H22: tolerance: 078.22423.05FD; signal model: Graser_C9334
C9335 = C402H22: tolerance: 078.22423.05FD; signal model: Graser_C9335
C9336 = C402H22: tolerance: 078.22423.05FD; signal model: Graser_C9336
C9337 = C402H22: tolerance: 078.22423.05FD; signal model: Graser_C9337
C9338 = C402H22: tolerance: 078.22423.05FD; signal model: Graser_C9338
C9401 = C402H22: tolerance: 078.22423.05FD; signal model: Graser_C9401
C9402 = C402H22: tolerance: 078.22423.05FD; signal model: Graser_C9402
C9406 = C402H22: tolerance: 078.22423.05FD; signal model: Graser_C9406
C9407 = C402H22: tolerance: 078.22423.05FD; signal model: Graser_C9407
C9501 = C402H22: tolerance: 78.10421.2FLDL; signal model: Graser_C9501
C9502 = C402H22: tolerance: 78.10421.2FLDL; signal model: Graser_C9502
C9503 = C402H22: tolerance: 78.10421.2FLDL; signal model: Graser_C9503
C9504 = C402H22: tolerance: 78.10421.2FLDL; signal model: Graser_C9504
CPU1 = SKTBGA1151R754612-UH369: tolerance: 062.10015.0161
D2501 D2601 D2602 D5601 D6301 D6302 = SOD323AKH38: tolerance: 83.R5003.H8H
D2502 D4303 = SOT-23-9H44: tolerance: 75.00054.A7D
D2701 = SOD-523-4H28: tolerance: 75.05125.070
D2901 = SOT23-2D4-123H44: tolerance: 075.00054.0A7D
D4201 = D4626-D914AKH44: tolerance: 083.00240.008M
D5301 = D5126145AKH91: tolerance: 83.1R004.N8M
DB2001 R803 R2102 R6308 R9101 R9104 = R603H22: tolerance: 63.00000.00L
DIMM1 DIMM2 = AH08847-A9L2-4M: tolerance: 022.10010.0761
EU3201-EU3204 EU3803 EU3901 = SOT-6-1H58: tolerance: 075.00199.007C
EU3801 EU3802 EU5601-EU5603 = DFN10G2510H26: tolerance: 75.01045.073
EU5901 EU5902 = SOT-6H58: tolerance: 075.02304.0C7C
F3301 F5901 = POLYSW-2114H30: tolerance: 69.48001.081
FANC1 = P254-1104A0ADKP-W: tolerance: 021.60305.0104
FANS1 = HF2704F-RM1: tolerance: 021.60234.0104
FL2901-FL2903 L3001-L3006 = L402H24: tolerance: 68.00213.031
HDMI1 = SKT-HDMI23-150122-9-U: tolerance: 62.10078.641
HPMIC1 = 2SJ3062-004111F: tolerance: 022.10002.0N01
HS1901 HS1902 = HB9603E-DW: tolerance: 21.60564.102
HS2601-HS2608 = GEN315R158-8-F-C-S-U: tolerance: ZZ.SCREW.541
HS6301 = STF256R109H99: tolerance: 34.3NH01.001
JMP1 = 21S-92-03GB16: tolerance: 021.60308.0203
L2101 L2102 = L603H38: tolerance: 68.00230.131
L2701-L2703 = L603H38: tolerance: 68.00335.181
L5301 = L6060-6018H186: tolerance: 068.10110.1021
L5901 L5902 = L603H38: tolerance: 68.00335.101
L5903-L5905 = L1608-UH38: tolerance: 68.00084.B61
L9501-L9504 = L603H38: tolerance: 68.00335.091
LED1 = LED3640AK-1H160: tolerance: 83.05721.070
LPC1 = 87212-1400N: tolerance: 20.F0765.014
NGFF1 = AS0BC21-S40BE-7H: tolerance: 062.10003.0611
NGFF2 = AS0BC21-S85BM-7H: tolerance: 062.10003.0601
PC4406 PC4419 = C402H22: tolerance: 78.33034.1FLDL
PC4411 PC4423 = C402H22: tolerance: 78.33224.2FLDL
PC4413 PC4424 = C402H22: tolerance: 78.22124.2FLDL
PC4415 PC4425 PC4505 PC4510 PC4515 PC4520 PC4605 PC4610 PC4707 PC5014 PC5110 = C402H22: tolerance: 78.15224.2FLDL
PC4708 PC5013 PC5108 = C402H22: tolerance: 78.18034.1FLDL
PC4801 PC4802 PC5009 PC5011 PC5012 PC5201 PC5203 PC5204 = C805H50: tolerance: 78.10623.51LDL
PC4805 PC4811 PC5015 = C402H22: tolerance: 078.47322.02FD
PC5206 = C402H22: tolerance: 78.15134.1FL
PG4501-PG4508 PG4601-PG4604 PG4701 PG4901 PG4902 PG5005 PG5006 PR4701-PR4706 PR4801-PR4807 PR4809 PR4901-PR4906 PR4908 PR4910 PR4912 PR4914 PR4916 PR4918 PR4920 PR4922 PR4924 PR4925 PR4927 PR4929 PR4933 PR4934 PR4936-PR4940 PR4945-PR4949 PR5006 PR5008 PR5010-PR5013 PR5015 PR5017 PR5018 PR5020-PR5023 PR5026-PR5030 PR5117-PR5135 = GAP-CLOSE-PWR-3: tolerance: ZZ.CLOSE.001
PG4903 = GAP-CLOSE-PWR-2U: tolerance: ZZ.0TPAD.011
PL4501-PL4504 PL4601 PL4602 = RT-D6D3-1D4-103065H394: tolerance: 019.40016.0211
PL4701 = L7066-1830-UH119: tolerance: 68.R4710.10M
PL4901 PL4902 = RT-D6D6-6D6-108108H426: tolerance: 019.40027.0011
PL4903-PL4905 PL5002 PL5003 PL5104 PL5105 = L805H44: tolerance: 68.00335.111
PL5001 = RT-D6D4-1D9-103072H394: tolerance: 019.40016.0191
PL5101 = L115100-2030H158: tolerance: 68.1R51A.10E
PR4401 PR4470 = R603H22: tolerance: 64.2R205.55L
PR4402 PR4409 PR4442 R404 R1103 R1106 R1203 R1206 R1611 R2023 R3103 = R402H16: tolerance: 64.10015.6DL
PR4403 = R402H16: tolerance: 64.26125.6DL
PR4404 PR4416 PR4423 PR4445 PR4454 R402 R403 R1513 R2024 R2605 R2614 = R402H14: tolerance: 64.10005.6DL
PR4405 = R402H16: tolerance: 64.45R35.6DL
PR4406 PR4461 R3001 R3002 R3005 R3006 R3013 R3014 R5913-R5915 = R402H16: tolerance: 64.75R05.6DL
PR4407 PR4439 R5916 R5917 = R402H16: tolerance: 64.47R05.6DL
PR4408 PR4440 = R402H16: tolerance: 64.40215.6DL
PR4410 PR4435-PR4438 PR4459 PR4460 PR4715 PR4717 PR4808 PR4813 PR4815 R2905 R2906 = R402H14: tolerance: 64.10R05.6DL
PR4411 R418 R802 R9504 R9505 = R402H16: tolerance: 64.49R95.6DL
PR4412 PR4415 PR4419 PR4422 PR4426 PR4427 PR4429 PR4432 PR4434 PR4443 PR4446 PR4451 PR4960 R2460 R2706 R2707 R2709 R2711 R4212 = R402H16: tolerance: 64.10035.6DL
PR4413 PR4424 PR4441 PR4716 PR4956 PR4957 PR5116 PR5202 PR5206 R2411 R2413 R4217 R4219 R4304 R5920 = R402H16: tolerance: 64.10025.6DL
PR4414 PR4417 PR4421 PR4425 PR4444 PR4448 = R402H16: tolerance: 64.69815.6DL
PR4418 PR4447 PR4812 PR5019 PR5204 R407 R408 R410-R412 R417 R801 R809 R902 R903 R1105 R1205 R1701 R1702 R1815 R1818 R1822 R2006 R2008 R2034 R2036 R2039 R2048 R2420 R2422 R2426 R2434 R2438 R2439 R3102 R3814 R4006-R4010 R4013 R4015 R4019 R4021 R4024-R4026 R4201 R4202 R4302 R5003 R5101 R5911 R5912 R9112 R9301 R9401 R9402 R9901 R9902 R9916-R9921 = 0R0402-PAD-1: tolerance: ZZ.00PAD.M11
PR4420 = R402H16: tolerance: 64.30015.6DL
PR4428 = R402H16: tolerance: 64.30035.6DL
PR4430 R2403 R2405 R2412 R2465 R2469 R2470 R2473 = R402H16: tolerance: 64.30025.6DL
PR4431 PR4455 PR4466 PR4468 = NTC-402H24-U: tolerance: 69.60013.201
PR4433 = R402H16: tolerance: 64.35725.6DL
PR4449 PR4453 = R603: tolerance: 64.68125.55L
PR4450 = R402H16: tolerance: 64.36015.6DL
PR4452 = R402H16: tolerance: 64.29435.6DL
PR4456 = R402H16: tolerance: 64.13335.6DL
PR4457 = R402H16: tolerance: 64.24925.6DL
PR4458 = R402H16: tolerance: 64.42225.6DL
PR4462 R2415 R2416 = R402H16: tolerance: 64.20015.6DL
PR4463 PR4464 R409 R2009 R2010 = R402H16: tolerance: 64.49905.6DL
PR4465 = R402H16: tolerance: 64.47525.6DL
PR4467 PR4469 = R402H16: tolerance: 64.38325.6DL
PR4471 PR5025 R1521 R2466 R5609 R6316 R6317 = R402H16: tolerance: 64.20025.6DL
PR4501 PR4502 PR4505 PR4507 PR4508 PR4511 PR4513 PR4514 PR4517 PR4519 PR4520 PR4523 PR4601 PR4602 PR4605 PR4607 PR4608 PR4611 = R805H24: tolerance: 64.2R205.16L
PR4503 PR4509 PR4515 PR4521 PR4603 PR4609 PR4710 PR4959 PR4961 PR5004 PR5107 PR5109 R413 R416 R422 R805 R1502 R1505 R1506 R1508 R1509 R1522 R1601-R1605 R1610 R1704-R1706 R1709 R1712-R1714 R1801 R1803 R1805-R1807 R1809-R1811 R1902 R1904 R1910-R1912 R1917-R1919 R2001 R2002 R2007 R2015 R2016 R2018 R2041 R2044 R2303 R2305 R2312 R2314 R2419 R2421 R2425 R2427 R2430 R2432 R2435 R2448 R2449 R2452 R2453 R2462-R2464 R2476 R2478 R2701 R2716 R2717 R3807-R3809 R3812 R3813 R4001 R4020 R4022 R4204 R4207 R4213 R4216 R4305 R4801 R4803 R6304 R6306 R6311-R6314 R6318 R6402-R6404 R6406-R6408 R6411 R6414 R6416 R6420-R6423 R9110 R9113 R9501 R9507 R9509-R9512 = R402H16: tolerance: 63.10334.1DL
PR4504 PR4510 PR4516 PR4522 PR4604 PR4610 = R805H24: tolerance: 63.1R031.16L
PR4506 PR4512 PR4518 PR4524 PR4606 PR4612 R415 R2011 R2026 R2028 = R402H16: tolerance: 64.51R05.6DL
PR4707 PR4709 PR4712 PR4713 PR4932 PR4941-PR4944 PR4950 PR4951 PR5005 PR5007 PR5016 PR5108 PR5110 PR5113 PR5115 = R805H24: tolerance: 63.2R231.16L
PR4708 = R402H16: tolerance: 64.40225.6DL
PR4711 PR5112 = R402H16: tolerance: 64.47035.6DL
PR4714 PR5114 = R402H16: tolerance: 64.48715.6DL
PR4810 = R805H24: tolerance: 63.10133.16L
PR4811 = R402H16: tolerance: 64.22015.6DL
PR4814 = R402H16: tolerance: 64.47015.6DL
PR4816 = R402H16: tolerance: 64.24025.6DL
PR4952 = R402H16: tolerance: 64.78725.6DL
PR4953 = R402H16: tolerance: 64.62025.6DL
PR4954 = R402H16: tolerance: 64.66515.6DL
PR4955 = R402H16: tolerance: 64.15425.6DL
PR4958 R414 R806 R807 R810 R1515 R1516 R1920 R2049-R2058 R2406 R2410 R2467 R2475 R2619 R4002 R4004 R4206 R4218 R5910 R5921 = R402H16: tolerance: 63.10434.1DL
PR4962 = R402H16: tolerance: 64.28025.6DL
PR5001 = R402H16: tolerance: 64.2R205.6DL
PR5002 R2101 R2503 R2705 R2708 R2713 R3105 R5302 R9403 = 0R0603-PAD-1-U: tolerance: ZZ.00PAD.M21
PR5003 = R402H16: tolerance: 64.20535.6DL
PR5009 = R402H16: tolerance: 64.62035.6DL
PR5014 PR5201 PR5203 = 0R0805-PAD-1-U: tolerance: ZZ.00PAD.M31
PR5024 = R402H16: tolerance: 64.15825.6DL
PR5111 = R402H16: tolerance: 64.56025.6DL
PR5205 = R402H16: tolerance: 64.21525.6DL
PT4501 PT4504 PT4506 PT4601 PT4901 = ECAP-138D8-UH355: tolerance: 09.2771D.C8L
PT4502 PT4503 PT4505 PT4507 PT4508 PT4602-PT4605 PT4701 PT4702 PT4801 PT5001 PT5101 TC1101 = ECAP-100D6D3H375: tolerance: 09.8271V.08L
PT4902 PT4903 = SE3116H241: tolerance: 79.22710.30L
PU4401 = QFN52J6-G4D8-UH40: tolerance: 074.81220.0073
PU4501 PU4505 PU4509 PU4513 PU4601 PU4604 PU4802 PU4901 PU4903 PU5002 Q4201 = PPAK-8P-5262H40: tolerance: 084.36358.0037
PU4502 PU4506 PU4510 PU4514 PU4602 PU4605 = DFN8G2-G1309-UH40: tolerance: 074.81258.00E3
PU4503 PU4504 PU4507 PU4508 PU4511 PU4512 PU4515 PU4516 PU4603 PU4606 PU4904 PU4905 PU5003 = PPAK-8P-5262H40: tolerance: 084.36356.0037
PU4701 PU5101 = DFN10G3-G265175H32: tolerance: 74.08237.B73
PU4702 PU5102 = PPAK-8P-G5324H44-COLAY: tolerance: ZZ.00215.037
PU4801 = SOT-6H58: tolerance: 74.05611.03P
PU4902 = QFN20-G1D75H32: tolerance: 074.06575.0A43
PU5001 = QFN20-G1D75H32: tolerance: 074.08231.0073
PU5201 = SOIC8-G3530H63: tolerance: 74.05930.B3D
PWRSW1 = SFNSDAA1542T-U: tolerance: 022.40005.0091
Q801 Q5901 = SOT23DGS2D8H50: tolerance: 84.03418.A31
Q802 Q5601 Q6301 Q6401 U2404 U4002 U4202 U4801 U5601 U6401 U6402 = SOT-363H44: tolerance: 75.27002.F7C
Q2001 Q2701-Q2704 = SOT23CBE2D4H44: tolerance: 84.T3906.E11
Q2401 Q2402 Q2405 Q2406 Q2408 Q2901 Q3001 Q4002 Q4202 Q4204 U401 = SOT-363-1H44: tolerance: 75.03904.D7C
Q2403 Q2404 Q2409 Q4001 Q4301 = SOT23CBE2D4H44: tolerance: 84.T3904.H11
Q2407 Q4203 Q9101 U4003 U6302 U6305 = SOT23DGS2D4H44: tolerance: 84.2N702.J31
Q3801 = SOT-363H44: tolerance: 75.03904.A7C
R301 R602 R701 R1207 = R402H16: tolerance: 64.24R95.6DL
R401 = R402H16: tolerance: 64.56R25.6DL
R405 = R402H16: tolerance: 64.22005.6DL
R419 = R402H16: tolerance: 64.60415.6DL
R420 = R402H16: tolerance: 64.28015.6DL
R421 R901 = R402H16: tolerance: 64.20R05.6DL
R423-R426 R1703 R1708 R2003 R2012-R2014 R2037 R2038 R2311 R2318 R2325 R2436 R2437 R2450 R2459 R2461 R2501 R2502 R2506 R2718 R2719 R2902 R2908 R2910 R3008 R3010 R4023 R9903 R9906-R9908 R9910 R9913 = R402H16: tolerance: 63.10234.1DL
R601 R1204 = R402H16: tolerance: 64.2R005.6DL
R702 = R402H16: tolerance: 63.20034.1DL; signal model: Graser_R702
R804 R1511 R2474 R2702 R4203 R4802 = R402H16: tolerance: 63.47334.1DL
R808 R2035 R2043 R2301 R2302 R2307 R2308 R2319 R2321 R2326 R2328 R2331 R2332 R2431 R2601 R2615 R2704 R2903 R2904 R3811 R3818 R4205 R5305 R5901-R5909 R5918 R5919 R6401 R6410 R6412 = R402H16: tolerance: 63.47234.1DL
R1101 R1201 = R402H16: tolerance: 64.24005.6DL
R1102 R1202 R1808 R2004 R2046 R2047 R2306 R2477 R2612 R2715 R3815-R3817 R4214 R4303 R5001 R5002 R6202 R6203 R6319 R6320 R6801 R6802 R9111 R9201 R9202 R9904 R9905 R9911 R9914 = R402H16: tolerance: 63.R0034.1DL
R1104 R5601-R5608 = R402H16: tolerance: 63.47134.1DL
R1503 R1901 R2402 R2604 R2617 R4017 R4018 = R402H16: tolerance: 64.82015.6DL
R1504 R1517 R1519 R1913 R2029 R2031-R2033 R2433 R6405 R9502 R9503 = R402H16: tolerance: 63.33034.1DL
R1507 R5610 = R402H16: tolerance: 63.10534.1DL
R1512 R9912 = R402H16: tolerance: 64.15005.6DL
R1514 = R402H16: tolerance: 64.20005.6DL
R1518 R1520 R1914-R1916 R2401 R2407 R9203 R9508 = R402H16: tolerance: 63.22034.1DL
R1609 = R402H16: tolerance: 64.11305.6DL
R1710 = R402H16: tolerance: 64.61905.6DL
R1711 = R402H16: tolerance: 63.30034.1DL
R1802 = R402H16: tolerance: 64.60R45.6DL
R1812 R4211 = R402H16: tolerance: 63.20434.1DL
R1814 = R603H22: tolerance: 63.10633.15L
R1906-R1908 R2045 R2324 R2327 R2329 R2603 R2616 R2901 R3011 R3012 R9909 R9922 = R402H16: tolerance: 63.22234.1DL
R2017 = R402H16: tolerance: 63.33034.1DL; signal model: Graser_R2017
R2019 = R402H16: tolerance: 63.33034.1DL; signal model: Graser_R2019
R2020 = R402H16: tolerance: 63.33034.1DL; signal model: Graser_R2020
R2021 R2030 R2504 = R402H16: tolerance: 64.15015.6DL
R2022 = R402H16: tolerance: 63.33034.1DL; signal model: Graser_R2022
R2025 = R402H16: tolerance: 63.30034.1DL; signal model: Graser_R2025
R2027 = R402H16: tolerance: 63.30034.1DL; signal model: Graser_R2027
R2040 R2042 = R402H16: tolerance: 64.30125.6DL
R2201 = R402H16: tolerance: 64.30R15.6DL
R2304 R2309 R2310 R2313 R2315-R2317 R2320 R2322 R2323 R2330 R2442 R2602 R2618 R4003 = R402H16: tolerance: 63.20334.1DL
R2404 R2414 R2417 = R402H16: tolerance: 64.91015.6DL
R2408 R3107 = R402H16: tolerance: 64.68005.6DL
R2409 R2472 = R402H16: tolerance: 64.68015.6DL
R2423 = R402H16: tolerance: 64.71515.6DL
R2424 = R402H16: tolerance: 64.33025.6DL
R2428 = R402H16: tolerance: 64.43R25.6DL
R2429 = R402H16: tolerance: 64.16005.6DL
R2446 = R402H16: tolerance: 64.33035.6DL
R2458 = R402H16: tolerance: 63.75034.1DL
R2468 = R402H16: tolerance: 64.16025.6DL
R2471 = R402H16: tolerance: 64.16515.6DL
R2505 = R402H16: tolerance: 64.45325.6DL
R2611 = R402H16: tolerance: 64.95315.6DL
R2613 = R402H16: tolerance: 64.10525.6DL
R2703 = R402H16: tolerance: 63.33034.1DL; signal model: Graser_R2703
R2710 R2712 = R402H16: tolerance: 64.20035.6DL
R2714 R4208 = R402H16: tolerance: 64.22035.6DL
R2907 R2909 R3003 R3004 R3007 R3009 R3015 R3016 R4005 R4011 = R402H16: tolerance: 63.22334.1DL
R3101 = R402H16: tolerance: 64.24915.6DL
R3104 = R603H22: tolerance: 64.10045.55L
R3106 = R402H16: tolerance: 64.15025.6DL
R3201 R3202 R4014 R4016 = R402H16: tolerance: 64.24905.6DL
R3203 = 0R1210-4P-PAD: tolerance: ZZ.00PAD.I21; signal model: Graser_R3203
R3204 = R603H22: tolerance: 63.51133.15L
R3205 = 0R1210-4P-PAD: tolerance: ZZ.00PAD.I21; signal model: Graser_R3205
R3206 = 0R1210-4P-PAD: tolerance: ZZ.00PAD.I21; signal model: Graser_R3206
R3207 = 0R1210-4P-PAD: tolerance: ZZ.00PAD.I21; signal model: Graser_R3207
R3301 = 0R0402-PAD-1: tolerance: ZZ.00PAD.M11; signal model: Graser_R3301
R3302 = R402H16: tolerance: 64.62015.6DL
R3303 = 0R1210-4P-PAD: tolerance: ZZ.00PAD.I21; signal model: Graser_R3303
R3801 = 0R1210-4P-PAD: tolerance: ZZ.00PAD.I21; signal model: Graser_R3801
R3802 = 0R1210-4P-PAD: tolerance: ZZ.00PAD.I21; signal model: Graser_R3802
R3804 = 0R1210-4P-PAD: tolerance: ZZ.00PAD.I21; signal model: Graser_R3804
R3806 = 0R1210-4P-PAD: tolerance: ZZ.00PAD.I21; signal model: Graser_R3806
R3810 R4209 R4210 R4215 = R402H16: tolerance: 64.22025.6DL
R5301 = R2010-2H28: tolerance: 64.R1505.GIL
R5303 = R402H16: tolerance: 64.19615.6DL
R5304 = R402H16: tolerance: 64.16925.6DL
R6301 = R402H16: tolerance: 64.60425.6DL
R6302 R6315 = R402H16: tolerance: 64.75025.6DL
R6409 = R1206H26: tolerance: 63.15132.11L
R6413 = R1206H24: tolerance: 63.10132.11L
R6418 = R603H22: tolerance: 63.36134.15L
R9105 = R402H16: tolerance: 63.33034.1DL; signal model: Graser_R9105
R9106 = R402H16: tolerance: 63.33034.1DL; signal model: Graser_R9106
R9107 = R402H16: tolerance: 63.33034.1DL; signal model: Graser_R9107
R9108 = 0R0402-PAD-1: tolerance: ZZ.00PAD.M11; signal model: Graser_R9108
R9204 R9205 = R402H16: tolerance: 63.82234.1DL
R9506 = R603H22: tolerance: 63.12334.15L
R9915 = R402H16: tolerance: 63.51034.1DL
RJ45R1 = RUA1JA-KJKC-DE0-0R: tolerance: 022.10001.0E11
RN1601 = ARES8-CN24-UH22: tolerance: 66.10336.B8L
RN2401-RN2403 RN9503-RN9506 = ARES8-CN24H20: tolerance: 66.82236.A8L
RN2501 = SMD-ARES4H18: tolerance: 66.33036.04L; signal model: Graser_RN2501
RN2502 = ARES8-CN24-UH20: tolerance: 66.33036.A8L; signal model: Graser_RN2502
RN5601 RN5901 = ARES2H16: tolerance: 66.22236.04L
RN9501 RN9502 = SMD-ARES4: tolerance: 66.82236.04L
SATA1 = LE18077-Z55D-4F: tolerance: 020.80129.0007
SATA2 = ABA-SAT-010-K04-U: tolerance: 20.81274.007
SATA3 SATA4 = LE18077-Z55D-4F: tolerance: 020.80128.0007
SATAP1 SATAP2 = 733-71-06TB18: tolerance: 020.80826.0006
SB1 = BGA874M250240H60: tolerance: ZZ.CANON.001
SD1 = WK21921-151146-7H: tolerance: 062.10002.0341
SLOT1 SLOT3 = AAA-PCI-003-K45: tolerance: 20.50394.036
SLOT2 = AAA-PCI-190-K10: tolerance: 020.50227.0164
SLOT4 = 10-00870-1A61-A: tolerance: 020.50091.0120
SSKT1 = SKT-SOIC8-1H211: tolerance: 62.10076.031
SSKT2 = SKT-SOIC16-153139H258: tolerance: 062.10029.0051
TC3201 TC3801 TC3901 TC5301 = ECAP-100D6D3H493: tolerance: 09.2271D.L16
TP401-TP416 TP601 TP701 TP901-TP907 TP1501 TP1504-TP1506 TP2001 TP2101 TP2102 TP2201 TP2202 TP2501 TP2502 = TPAD28: tolerance: ZZ.PAD28.XXX
TP3101-TP3103 TP9106 = TPAD30: tolerance: ZZ.PAD30.XXX
TR3201 = L125100-4PH24: tolerance: 068.24900.2001; signal model: Graser_TR3201
TR3202 = L125100-4PH24: tolerance: 068.24900.2001; signal model: Graser_TR3202
TR3801 = L125100-4PH24: tolerance: 068.24900.2001; signal model: Graser_TR3801
TR3802 = L125100-4PH24: tolerance: 068.24900.2001; signal model: Graser_TR3802
TR3901 = L125100-4PH24: tolerance: 068.24900.2001; signal model: Graser_TR3901
TR3902 = L125100-4PH24: tolerance: 068.24900.2001; signal model: Graser_TR3902
TR5601 = L125100-4PH26: tolerance: 068.12102.2001; signal model: Graser_TR5601
TR5602 = L125100-4PH26: tolerance: 068.12102.2001; signal model: Graser_TR5602
TR5603 = L125100-4PH26: tolerance: 068.12102.2001; signal model: Graser_TR5603
TR5604 = L125100-4PH26: tolerance: 068.12102.2001; signal model: Graser_TR5604
U2001 U2003 U2402 U4005 U4008 U4301 = SOT-363H44: tolerance: 073.01G97.000J
U2002 = SSOIC8-4H36: tolerance: 73.01G74.00F
U2401 = PFPCC128-5H48: tolerance: 71.05553.00E
U2403 = SC70-5H44: tolerance: 73.01G14.IHG
U2405 = SC70-5H44: tolerance: 073.7SZ32.000G
U2501 = SOIC8-1H86: tolerance: 072.25673.0001
U2502 = SOIC16-6H105: tolerance: 072.25673.0A01
U2601 = SOT-23-5H56: tolerance: 74.00709.A7F
U2602 U4009 U4010 = SC70-5H44: tolerance: 73.01G08.DHG
U2701 = LQFP48H63: tolerance: 071.03820.000G
U3101 = QFN32J4-G2D85H36: tolerance: 71.08111.U03
U3201 U3801 U3901 = SOT-23-5H58: tolerance: 074.00524.0B9F
U3301 = QFN24-G2D5H40-U: tolerance: 71.05170.003
U4001 U4004 U4006 U4007 = SC70-5H44: tolerance: 73.01G08.AAH
U4201 = SON14J3020-G2610H32: tolerance: 074.02331.0A93
U4203 = PPAK-8P-3232H36: tolerance: 84.07401.037
U5301 = SOIC8H69: tolerance: 74.34063.I41
U5602 = SOT23-2D4-312H48: tolerance: 074.02331.009B
U5901 = QFN32J4-G2D85H36: tolerance: 071.02166.0003
U6301 = SOT-23-5H51: tolerance: 74.09724.09F
U9101 = QFN32G5-G3D6H32: tolerance: 071.00750.M001
U9501 = LQFP128H63: tolerance: 71.08893.B0G
USB2R1 = SKT-USB12-157183: tolerance: 22.10321.W41
USB3F1 USB3F2 = SKT-USB11-138166: tolerance: 022.10005.0F41
VGA1 = VDS075W-D307-00A3F2B: tolerance: 020.20064.0015
